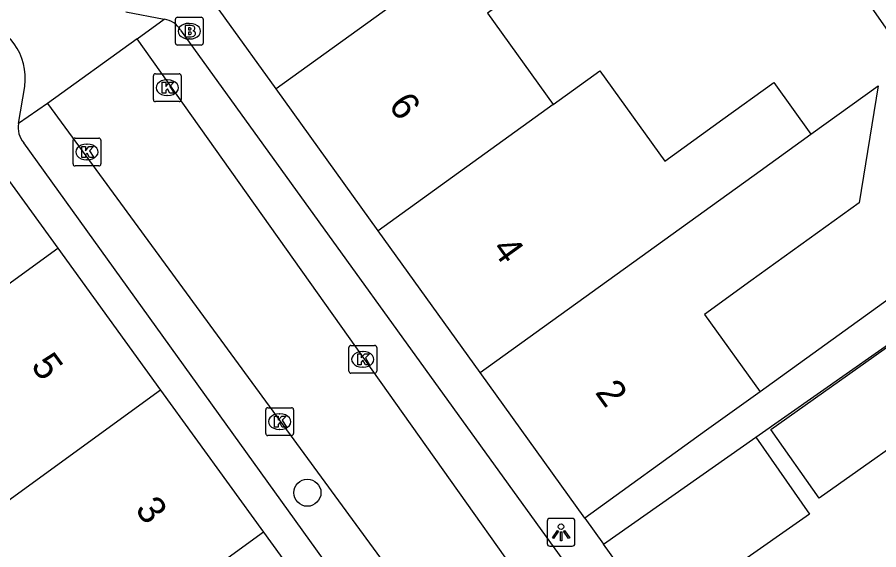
# Model space of a CAD drawing. Extents: x 161882 to 162509, y 381687 to 382379.
# Drawn here: x 162192.56 to 162223.52, y 381923.63 to 381942.76 of the extents above; entities that cross this region are included whole.
import ezdxf

# ---------------------------------------------------------------- set-up
doc = ezdxf.new("R2010")
doc.units = 0
for name, color, linetype in [('IMGEO_Boom', 7, 'Continuous'), ('IMGEO_Brandkraan', 7, 'Continuous'), ('IMGEO_Kolk', 7, 'Continuous'), ('IMGEO_Lichtpunt', 7, 'Continuous'), ('IMGEO_Pand', 7, 'Continuous'), ('IMGEO_Pand_nummerreeks', 7, 'Continuous'), ('IMGEO_Rijbaan_lokaal_open', 7, 'Continuous'), ('IMGEO_Voetpad_open', 7, 'Continuous')]:
    doc.layers.add(name, color=color, linetype=linetype)

msp = doc.modelspace()

# ---------------------------------------------------------------- linework, layer by layer
at = {"layer": 'IMGEO_Boom'}
msp.add_circle((162202.985, 381925.681), 0.489, dxfattribs=at)
at = {"layer": 'IMGEO_Brandkraan'}
for p, q in [((162198.243, 381941.829), (162198.243, 381942.681)), ((162198.318, 381942.755), (162199.17, 381942.755)), ((162199.244, 381942.681), (162199.244, 381941.829)), ((162198.731, 381942.535), (162198.756, 381942.535)), ((162199.17, 381941.755), (162198.318, 381941.755)), ((162198.754, 381941.975), (162198.729, 381941.975))]:
    msp.add_line(p, q, dxfattribs=at)
for points in [[(162198.243, 381941.829), (162198.243, 381942.681)], [(162198.318, 381942.755), (162199.17, 381942.755)], [(162199.244, 381942.681), (162199.244, 381941.829)], [(162198.591, 381942.455), (162198.591, 381942.055), (162198.804, 381942.055)], [(162198.822, 381942.455), (162198.591, 381942.455)], [(162198.77, 381942.374), (162198.716, 381942.374), (162198.716, 381942.298)], [(162198.716, 381942.298), (162198.769, 381942.298)], [(162198.778, 381942.222), (162198.716, 381942.222), (162198.716, 381942.141)], [(162198.716, 381942.141), (162198.778, 381942.141)], [(162199.17, 381941.755), (162198.318, 381941.755)]]:
    msp.add_lwpolyline(points, dxfattribs=at)
for centre, radius, start, end in [((162198.32, 381942.679), 0.0765, 91.552, 178.448), ((162198.32, 381942.679), 0.0765, 91.552, 178.448), ((162199.168, 381942.679), 0.0765, 1.552, 88.448), ((162199.168, 381942.679), 0.0765, 1.552, 88.448), ((162198.771, 381942.336), 0.0379, 267.8285, 90.9355), ((162198.826, 381942.31), 0.145, 59.4692, 91.5367), ((162198.851, 381942.357), 0.0922, 285.5137, 58.1501), ((162198.779, 381942.181), 0.0404, 269.8759, 90.5077), ((162198.81, 381942.306), 0.251, 268.6676, 293.5347), ((162198.856, 381942.165), 0.105, 301.3115, 78.989), ((162198.32, 381941.831), 0.0765, 181.552, 268.448), ((162198.32, 381941.831), 0.0765, 181.552, 268.448), ((162199.168, 381941.831), 0.0765, 271.552, 358.448), ((162199.168, 381941.831), 0.0765, 271.552, 358.448)]:
    msp.add_arc(centre, radius, start, end, dxfattribs=at)
for centre, major_axis, ratio, start_param, end_param in [((162198.73, 381942.255), (-0.387, 0.002), 0.722429, 4.712389, 7.853982), ((162198.755, 381942.255), (-0.39, 0.002), 0.717154, 1.570796, 4.712389)]:
    msp.add_ellipse(centre, major_axis=major_axis, ratio=ratio, start_param=start_param, end_param=end_param, dxfattribs=at)
at = {"layer": 'IMGEO_Kolk'}
for p, q in [((162197.451, 381939.798), (162197.451, 381940.65)), ((162197.526, 381940.724), (162198.378, 381940.724)), ((162197.939, 381940.504), (162197.964, 381940.504)), ((162198.452, 381940.65), (162198.452, 381939.798)), ((162197.962, 381939.944), (162197.937, 381939.944)), ((162198.378, 381939.724), (162197.526, 381939.724)), ((162194.564, 381937.488), (162194.564, 381938.34)), ((162194.639, 381938.414), (162195.491, 381938.414)), ((162195.565, 381938.34), (162195.565, 381937.488)), ((162195.052, 381938.194), (162195.077, 381938.194)), ((162195.491, 381937.414), (162194.639, 381937.414)), ((162195.075, 381937.634), (162195.05, 381937.634)), ((162204.476, 381930.044), (162204.476, 381930.896)), ((162204.551, 381930.97), (162205.403, 381930.97)), ((162205.477, 381930.896), (162205.477, 381930.044)), ((162204.964, 381930.75), (162204.989, 381930.75)), ((162205.403, 381929.97), (162204.551, 381929.97)), ((162204.987, 381930.19), (162204.962, 381930.19)), ((162201.563, 381928.733), (162202.415, 381928.733)), ((162201.488, 381927.807), (162201.488, 381928.659)), ((162201.976, 381928.513), (162202.001, 381928.513)), ((162202.489, 381928.659), (162202.489, 381927.807)), ((162201.999, 381927.953), (162201.974, 381927.953)), ((162202.415, 381927.733), (162201.563, 381927.733))]:
    msp.add_line(p, q, dxfattribs=at)
for points in [[(162197.451, 381939.798), (162197.451, 381940.65)], [(162197.526, 381940.724), (162198.378, 381940.724)], [(162198.452, 381940.65), (162198.452, 381939.798)], [(162197.772, 381940.424), (162197.895, 381940.424), (162197.895, 381940.273), (162198.025, 381940.424), (162198.189, 381940.424), (162198.043, 381940.273), (162198.196, 381940.024), (162198.044, 381940.024), (162197.959, 381940.188), (162197.895, 381940.121), (162197.895, 381940.024), (162197.772, 381940.024), (162197.772, 381940.424)], [(162198.378, 381939.724), (162197.526, 381939.724)], [(162194.564, 381937.488), (162194.564, 381938.34)], [(162194.639, 381938.414), (162195.491, 381938.414)], [(162195.565, 381938.34), (162195.565, 381937.488)], [(162194.885, 381938.114), (162195.008, 381938.114), (162195.008, 381937.963), (162195.138, 381938.114), (162195.302, 381938.114), (162195.156, 381937.963), (162195.309, 381937.714), (162195.157, 381937.714), (162195.072, 381937.878), (162195.008, 381937.811), (162195.008, 381937.714), (162194.885, 381937.714), (162194.885, 381938.114)], [(162195.491, 381937.414), (162194.639, 381937.414)], [(162204.476, 381930.044), (162204.476, 381930.896)], [(162204.551, 381930.97), (162205.403, 381930.97)], [(162205.477, 381930.896), (162205.477, 381930.044)], [(162204.797, 381930.67), (162204.92, 381930.67), (162204.92, 381930.519), (162205.05, 381930.67), (162205.214, 381930.67), (162205.068, 381930.519), (162205.221, 381930.27), (162205.069, 381930.27), (162204.984, 381930.434), (162204.92, 381930.367), (162204.92, 381930.27), (162204.797, 381930.27), (162204.797, 381930.67)], [(162205.403, 381929.97), (162204.551, 381929.97)], [(162201.563, 381928.733), (162202.415, 381928.733)], [(162201.488, 381927.807), (162201.488, 381928.659)], [(162201.809, 381928.433), (162201.932, 381928.433), (162201.932, 381928.282), (162202.062, 381928.433), (162202.226, 381928.433), (162202.08, 381928.282), (162202.233, 381928.033), (162202.081, 381928.033), (162201.996, 381928.197), (162201.932, 381928.13), (162201.932, 381928.033), (162201.809, 381928.033), (162201.809, 381928.433)], [(162202.489, 381928.659), (162202.489, 381927.807)], [(162202.415, 381927.733), (162201.563, 381927.733)]]:
    msp.add_lwpolyline(points, dxfattribs=at)
for centre, start, end in [((162197.528, 381940.648), 91.552, 178.448), ((162197.528, 381940.648), 91.552, 178.448), ((162198.376, 381940.648), 1.552, 88.448), ((162198.376, 381940.648), 1.552, 88.448), ((162197.528, 381939.8), 181.552, 268.448), ((162197.528, 381939.8), 181.552, 268.448), ((162198.376, 381939.8), 271.552, 358.448), ((162198.376, 381939.8), 271.552, 358.448), ((162194.641, 381938.338), 91.552, 178.448), ((162194.641, 381938.338), 91.552, 178.448), ((162195.489, 381938.338), 1.552, 88.448), ((162195.489, 381938.338), 1.552, 88.448), ((162194.641, 381937.49), 181.552, 268.448), ((162194.641, 381937.49), 181.552, 268.448), ((162195.489, 381937.49), 271.552, 358.448), ((162195.489, 381937.49), 271.552, 358.448), ((162204.553, 381930.894), 91.552, 178.448), ((162204.553, 381930.894), 91.552, 178.448), ((162205.401, 381930.894), 1.552, 88.448), ((162205.401, 381930.894), 1.552, 88.448), ((162204.553, 381930.046), 181.552, 268.448), ((162204.553, 381930.046), 181.552, 268.448), ((162205.401, 381930.046), 271.552, 358.448), ((162205.401, 381930.046), 271.552, 358.448), ((162201.565, 381928.657), 91.552, 178.448), ((162201.565, 381928.657), 91.552, 178.448), ((162202.413, 381928.657), 1.552, 88.448), ((162202.413, 381928.657), 1.552, 88.448), ((162201.565, 381927.809), 181.552, 268.448), ((162201.565, 381927.809), 181.552, 268.448), ((162202.413, 381927.809), 271.552, 358.448), ((162202.413, 381927.809), 271.552, 358.448)]:
    msp.add_arc(centre, 0.0765, start, end, dxfattribs=at)
for centre, major_axis, ratio, start_param, end_param in [((162197.938, 381940.224), (-0.387, 0.002), 0.722429, 4.712389, 7.853982), ((162197.963, 381940.224), (-0.39, 0.002), 0.717154, 1.570796, 4.712389), ((162195.051, 381937.914), (-0.387, 0.002), 0.722429, 4.712389, 7.853982), ((162195.076, 381937.914), (-0.39, 0.002), 0.717154, 1.570796, 4.712389), ((162204.963, 381930.47), (-0.387, 0.002), 0.722429, 4.712389, 7.853982), ((162204.988, 381930.47), (-0.39, 0.002), 0.717154, 1.570796, 4.712389), ((162201.975, 381928.233), (-0.387, 0.002), 0.722429, 4.712389, 7.853982), ((162202, 381928.233), (-0.39, 0.002), 0.717154, 1.570796, 4.712389)]:
    msp.add_ellipse(centre, major_axis=major_axis, ratio=ratio, start_param=start_param, end_param=end_param, dxfattribs=at)
at = {"layer": 'IMGEO_Lichtpunt'}
for p, q in [((162212.503, 381924.756), (162211.695, 381924.756)), ((162212.503, 381924.756), (162211.695, 381924.756)), ((162211.601, 381924.661), (162211.601, 381923.854)), ((162211.601, 381924.661), (162211.601, 381923.854)), ((162212.597, 381923.854), (162212.597, 381924.661)), ((162212.597, 381923.854), (162212.597, 381924.661)), ((162211.695, 381923.76), (162212.503, 381923.76)), ((162211.695, 381923.76), (162212.503, 381923.76))]:
    msp.add_line(p, q, dxfattribs=at)
for points in [[(162211.975, 381924.325), (162212.014, 381924.297), (162211.826, 381924.035), (162211.788, 381924.062), (162211.975, 381924.325)], [(162212.077, 381924.277), (162212.124, 381924.277), (162212.124, 381923.955), (162212.077, 381923.955), (162212.077, 381924.277)], [(162212.187, 381924.297), (162212.225, 381924.324), (162212.412, 381924.062), (162212.373, 381924.034), (162212.187, 381924.297)]]:
    msp.add_lwpolyline(points, dxfattribs=at)
msp.add_circle((162212.1, 381924.459), 0.0994, dxfattribs=at)
for centre, start, end in [((162211.695, 381924.661), 90, 180), ((162211.695, 381924.661), 90, 180), ((162212.503, 381924.661), 0, 90), ((162212.503, 381924.661), 0, 90), ((162211.695, 381923.854), 180, 270), ((162211.695, 381923.854), 180, 270), ((162212.503, 381923.854), 270, 0), ((162212.503, 381923.854), 270, 360)]:
    msp.add_arc(centre, 0.0946, start, end, dxfattribs=at)
at = {"layer": 'IMGEO_Pand'}
for points in [[(162211.962, 381947.457), (162201.866, 381940.184)], [(162211.962, 381947.457), (162213.266, 381945.647), (162211.221, 381944.174), (162209.457, 381942.903), (162211.822, 381939.62)], [(162224.7, 381941.042), (162223.336, 381942.994), (162222.907, 381943.607), (162226.816, 381946.365), (162228.677, 381943.848)], [(162201.866, 381940.184), (162198.203, 381945.276)], [(162211.822, 381939.62), (162213.5, 381940.829), (162215.834, 381937.589), (162217.916, 381939.089), (162219.743, 381940.406), (162221.079, 381938.552)], [(162205.532, 381935.088), (162201.866, 381940.184)], [(162221.079, 381938.552), (162223.492, 381940.291), (162222.809, 381936.085), (162218.922, 381933.285), (162217.252, 381932.082), (162219.25, 381929.308)], [(162190.227, 381939.679), (162194.014, 381934.46)], [(162211.822, 381939.62), (162205.532, 381935.088)], [(162209.198, 381929.992), (162219.251, 381937.235), (162221.079, 381938.552)], [(162209.198, 381929.992), (162205.532, 381935.088)], [(162181.737, 381925.793), (162188.26, 381930.286), (162194.014, 381934.46)], [(162194.014, 381934.46), (162197.713, 381929.361)], [(162221.38, 381925.484), (162219.634, 381927.948), (162224.002, 381931.042), (162225.747, 381928.578), (162221.38, 381925.484)], [(162212.953, 381924.771), (162209.198, 381929.992)], [(162197.713, 381929.361), (162191.96, 381925.187), (162191.766, 381925.054)], [(162197.713, 381929.361), (162201.412, 381924.261)], [(162219.25, 381929.308), (162217.332, 381927.926), (162212.953, 381924.771)], [(162213.628, 381923.833), (162219.1, 381927.669)], [(162219.1, 381927.669), (162221.034, 381924.911), (162215.596, 381921.098)], [(162201.412, 381924.261), (162195.66, 381920.088), (162187.121, 381913.922)], [(162201.412, 381924.261), (162205.199, 381919.042), (162205.042, 381918.928)], [(162215.596, 381921.098), (162213.628, 381923.833)]]:
    msp.add_lwpolyline(points, dxfattribs=at)
at = {"layer": 'IMGEO_Rijbaan_lokaal_open'}
for points in [[(162196.463, 381942.947), (162197.845, 381942.684)], [(162196.865, 381941.979), (162197.845, 381942.684)], [(162196.865, 381941.979), (162193.648, 381939.662)], [(162221.938, 381906.686), (162196.865, 381941.979)], [(162192.603, 381938.942), (162192.827, 381940.274)], [(162193.648, 381939.662), (162192.603, 381938.942)], [(162193.648, 381939.662), (162211.441, 381915.372)]]:
    msp.add_lwpolyline(points, dxfattribs=at)
msp.add_arc((162190.741, 381940.572), 2.107, 351.8755, 79.3553, dxfattribs=at)
at = {"layer": 'IMGEO_Voetpad_open'}
for points in [[(162229.626, 381942.938), (162232.631, 381938.95), (162219.25, 381929.308)], [(162198.431, 381942.294), (162212.193, 381923.231)], [(162219.1, 381927.669), (162234.406, 381938.399), (162239.696, 381931.008)], [(162206.572, 381919.103), (162192.794, 381938.247)], [(162212.953, 381924.771), (162213.628, 381923.833)]]:
    msp.add_lwpolyline(points, dxfattribs=at)
for centre, radius, start, end in [((162197.74, 381941.891), 0.8, 30.2669, 82.4433), ((162193.451, 381938.801), 0.86, 170.5782, 220.1552)]:
    msp.add_arc(centre, radius, start, end, dxfattribs=at)

# ---------------------------------------------------------------- texts
at = {"layer": 'IMGEO_Pand_nummerreeks'}
for s, rotation, p in [('6', 305.7695, (162205.872, 381939.589)), ('4', 305.768, (162209.587, 381934.433)), ('5', 305.9606, (162193.025, 381930.237)), ('2', 305.7695, (162213.3, 381929.279)), ('3', 305.9586, (162196.769, 381925.078))]:
    msp.add_text(s, height=1, rotation=rotation, dxfattribs=at).set_placement(p)

doc.saveas('drawing.dxf')
